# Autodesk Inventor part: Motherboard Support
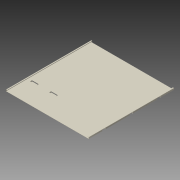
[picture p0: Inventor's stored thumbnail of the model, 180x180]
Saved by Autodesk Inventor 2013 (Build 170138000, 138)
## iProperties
Created: 2007-02
Part Number: Motherboard Support
Material: Allgemein
Document SubType Name: Sheet Metal
Designer: Autodesk, Inc.
Mass: 68.5716 g
Surface Area: 2752.43 cm^2
Volume: 68.5716 cm^3
Density: 1 g/cm^3
Sheet Metal Rule: 0.5 mm
Author: Autodesk, Inc.
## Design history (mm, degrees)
node "Contour Flange1"
cut "Cut1" dims "d23" = 0.5 (= Thickness), "d24" = 0
workplane "Work Plane1"
node "Face1"
bend "Bend3" dims "d39" = 0.5 (= BendReliefWidth), "d40" = 0.25 (= BendReliefDepth), "d41" = 1 (= MinimumRemnant), "d42" = 0.5 (= BendRadius), "d43" = 0.5 (= BendRadius), "SeamGap" = 0.01, "Thickness" = 0.5
bend "Bend4" dims "d44" = 0.5 (= BendReliefWidth), "d45" = 0.25 (= BendReliefDepth), "d46" = 1 (= MinimumRemnant), "d47" = 0.5 (= BendRadius), "d48" = 0.5 (= BendRadius), "SeamGap" = 0.01, "Thickness" = 0.5
bend "Bend5" dims "d49" = 0.5 (= BendReliefWidth), "d50" = 0.25 (= BendReliefDepth), "d51" = 1 (= MinimumRemnant), "d52" = 0.5 (= BendRadius), "d53" = 0.5 (= BendRadius), "SeamGap" = 0.01, "Thickness" = 0.5
bend "Bend6" dims "d54" = 0.5 (= BendReliefWidth), "d55" = 0.25 (= BendReliefDepth), "d56" = 1 (= MinimumRemnant), "d57" = 0.5 (= BendRadius), "d58" = 0.5 (= BendRadius), "SeamGap" = 0.01, "Thickness" = 0.5
cut "Cut2" dims "d67" = 0.5 (= Thickness), "d68" = 0
body "Solid1"
sketch "Sketch1"
  geometry: L1 (-173, 3.5)-(-178, 3.5); L2 (-178, 3.5)-(-178, -3.5); L3 (-178, -3.5)-(178, -3.5); L4 (178, -3.5)-(178, 3.5); L5 (178, 3.5)-(173, 3.5); L6 (178, -3.5)-(-178, 3.5); 2 further points
  constraints: 12 end point, 2 equal length, 2 parallel, 1 coincident, 1 collinear, 1 horizontal, 1 midpoint, 1 perpendicular
  dimensions: "d0" = 356 distance of L2.end L3.end; "d1" = 7 distance of L1.end L2.end; "d2" = 5 distance of L1.start L1.end
face "Plate1" dims "d3" = 0.5 (= BendReliefWidth), "d4" = 0.25 (= BendReliefDepth), "d5" = 1 (= MinimumRemnant), "d6" = 0.5 (= BendRadius), "d7" = 366, "d8" = 0.5 (= BendRadius), "d9" = 1, "d10" = 2 (= CornerReliefSize), "d11" = 0.5 (= Thickness), "d69" = 0.5 (= JacobiRadiusSize), "SeamGap" = 0.01, "Thickness" = 0.5
bend "Bend1" dims "d3" = 0.5 (= BendReliefWidth), "d4" = 0.25 (= BendReliefDepth), "d5" = 1 (= MinimumRemnant), "d6" = 0.5 (= BendRadius), "d8" = 0.5 (= BendRadius), "d9" = 1, "SeamGap" = 0.01, "Thickness" = 0.5
feature "Corner1" dims "d9" = 1, "d10" = 2 (= CornerReliefSize), "d11" = 0.5 (= Thickness), "d69" = 0.5 (= JacobiRadiusSize)
sketch "Sketch2" dims "d21" = 10
  geometry: L1 (14, -88.2)-(44, -88.2); L2 (44, -88.2)-(44, -96.2); L3 (44, -96.2)-(14, -96.2); L4 (14, -96.2)-(14, -88.2); L5 (354, 0)-(0, 0) reference; L6 (-1, -366)-(-1, 0) reference; L7 (126, -96.2)-(96, -96.2); L8 (96, -96.2)-(96, -88.2); L9 (96, -88.2)-(126, -88.2); L10 (126, -88.2)-(126, -96.2)
  constraints: 16 end point, 2 horizontal, 2 parallel, 1 perpendicular, 8 other
  dimensions: "d12" = 30 distance of L2.end L3.end; "d13" = 8 distance of L3.end L1.start; "d14" = 88.2 distance between parallel lines of L5 L1; "d15" = 15 distance between parallel lines of L6 L4; "d18" = 82 distance of L2.end L7.start
sketch "Sketch3"
  geometry: L1 (18, -89.2)-(40, -89.2); L2 (40, -89.2)-(40, -95.2); L3 (40, -95.2)-(18, -95.2); L4 (18, -95.2)-(18, -89.2); L5 (100, -89.2)-(122, -89.2); L6 (122, -89.2)-(122, -95.2); L7 (122, -95.2)-(100, -95.2); L8 (100, -95.2)-(100, -89.2); L9 (44, -96.2)-(14, -96.2) reference; L10 (14, -96.2)-(14, -88.2) reference; L11 (14, -88.2)-(44, -88.2) reference; L12 (44, -88.2)-(44, -96.2) reference; L13 (126, -96.2)-(96, -96.2) reference; L14 (96, -96.2)-(96, -88.2) reference; L15 (96, -88.2)-(126, -88.2) reference; L16 (126, -88.2)-(126, -96.2) reference
  constraints: 16 end point, 4 parallel, 2 horizontal, 2 perpendicular
  dimensions: "d26" = 1 distance between parallel lines of L3 L9; "d27" = 1 distance between parallel lines of L11 L1 (= d26); "d28" = 4 distance between parallel lines of L10 L4; "d29" = 4 distance between parallel lines of L12 L2 (= d28); "d30" = 4 distance between parallel lines of L14 L8 (= d28); "d31" = 4 distance between parallel lines of L16 L6 (= d28); "d32" = 1 distance between parallel lines of L13 L7 (= d26); "d33" = 1 distance between parallel lines of L15 L5 (= d26)
face "Plate2" dims "d34" = 0.5 (= BendRadius), "d37" = 1 (= MinimumRemnant), "SeamGap" = 0.01, "Thickness" = 0.5
bend "Bend2" dims "d34" = 0.5 (= BendRadius), "d35" = 0.5 (= BendReliefWidth), "d36" = 0.25 (= BendReliefDepth), "d37" = 1 (= MinimumRemnant), "d38" = 0.5 (= BendRadius), "SeamGap" = 0.01, "Thickness" = 0.5
sketch "Sketch4"
  geometry: L1 (294, 4)-(308, 4); L2 (308, 4)-(308, -11); L3 (308, -11)-(294, -11); L4 (294, -11)-(294, 4); L5 (366, 5)-(0, 5) reference; L6 (366, 0)-(366, 5) reference; L7 (175, 4)-(189, 4); L8 (189, 4)-(189, -11); L9 (189, -11)-(175, -11); L10 (175, -11)-(175, 4); L11 (57.5, 4)-(71.5, 4); L12 (71.5, 4)-(71.5, -11); L13 (71.5, -11)-(57.5, -11); L14 (57.5, -11)-(57.5, 4)
  constraints: 24 end point, 6 parallel, 4 collinear, 3 horizontal, 3 perpendicular
  dimensions: "d59" = 15 distance of L3.end L1.start; "d60" = 14 distance of L2.end L3.end; "d61" = 1 distance between parallel lines of L5 L1; "d62" = 58 distance between parallel lines of L6 L2; "d63" = 119 distance between parallel lines of L8 L2; "d64" = 117.5 distance between parallel lines of L12 L8; "d65" = 14 distance of L8.end L9.end; "d66" = 14 distance of L11.start L11.end
other parameters: "BendRadius" = 0.5 (= Thickness), "BendReliefWidth" = 0.5 (= Thickness), "BendReliefDepth" = 0.25 (= 0.5 x Thickness), "CornerReliefSize" = 2 (= 4 x Thickness), "MinimumRemnant" = 1 (= 2 x Thickness), "TransitionRadius" = 0.5 (= BendRadius), "JacobiRadiusSize" = 0.5 (= Thickness), "d25" = 2, "GapSize" = 0.5 (= Thickness)
